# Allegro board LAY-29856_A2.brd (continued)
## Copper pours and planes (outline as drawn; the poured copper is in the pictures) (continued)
GND on TOP (solid shape): 50.31,35.8 51.45,35.8 51.72,35.53 51.75,35.42 51.66,35.36 51.36,35.21 51.26,34.9 51.26,34.87 50.79,34.4 50.79,33.64 49.72,32.57 49.61,32.55 49.55,32.65 49.55,33.53 49.64,33.53 49.64,33.78 49.68,33.78 49.68,34.29 49.64,34.29 49.64,34.8 49.68,34.8 49.68,35.31 49.64,35.31 49.64,35.56 49.56,35.56 49.56,35.81 50.3,35.81
GND on TOP (solid shape): 72.67,49.89 72.67,49.28 73.42,49.28 73.42,49.15 72.8,49.15 72.8,48.96 71.57,48.96 71.48,49.01 71.49,49.11 71.52,49.18 71.6,49.22 71.63,49.3 71.63,49.5 71.6,49.59 71.52,49.63 71.39,49.81 71.21,49.93 71.15,50.01 71.18,50.1 71.36,50.28 72.29,50.28
GND on TOP (solid shape): 118.99,61.08 118.75,60.62 118.93,60.13 118.95,60.02 118.86,59.96 118.03,59.96 117.96,60.02 117.94,60.13 118.03,60.2 118.59,60.2 118.59,61.22 118.53,61.27 118.52,61.35 118.54,61.42 118.54,61.5 118.54,61.52 118.88,61.86 118.99,61.86
GND on TOP (solid shape): 14.86,32.27 14.92,32.36 15.03,32.34 17.23,30.15 17.22,30.12 17.41,29.48 18.05,29.29 18.08,29.29 18.39,28.99 18.67,28.99 18.67,28.86 20.7,28.86 20.7,28.99 21.1,28.99 21.2,28.92 21.17,28.81 20.95,28.59 20.95,28.32 20.7,28.32 20.7,27.3 20.95,27.3 20.95,26.29 19.22,26.29 14.86,30.65
GND on TOP (solid shape): 105.73,48.2 105.84,48.23 105.9,48.13 105.9,47.35 95.81,37.26 95.79,37.26 95.39,37.06 95.38,36.61 95.38,36.51 95.3,36.46 95.2,36.46 95.12,36.51 95.12,36.61 95.17,36.91 95.01,37.17 95.01,37.48
GND on TOP (solid shape): 38.41,27.21 38.83,26.99 39.28,27.16 39.54,27.16 39.63,27.11 39.63,27.01 39.58,26.71 39.74,26.46 39.74,25.72 43.93,21.53 43.93,18.52 43.87,18.43 43.76,18.45 43.56,18.65 43.56,21.44 37.97,27.04 37.95,27.15 38.04,27.21
GND on TOP (solid shape): 81.27,24.24 81.03,24.24 81.03,24.28 80.52,24.28 80.52,24.24 80.26,24.24 80.26,24.02 80.15,24.02 79.87,23.74 79.87,23.67 79.81,23.57 79.7,23.6 79.66,23.63 79.61,23.71 79.64,23.79 79.69,23.83 79.75,23.92 79.77,24.02 79.77,24.26 79.75,24.36 79.69,24.45 79.69,24.45 79.66,24.56 79.75,24.62 79.96,24.83 80.01,24.92 80.03,25.02 80.03,25.13 81.27,25.13
GND on TOP (solid shape): 84.41,32.06 84.43,31.95 84.34,31.89 83.95,31.89 83.87,31.93 83.86,32.02 83.63,32.52 83.1,32.4 82.94,32.4 82.86,32.44 82.84,32.53 82.84,32.76 82.71,32.96 82.69,32.98 82.69,33 81,34.69 81,35.29 81.18,35.29
GND on TOP (solid shape): 9.73,49.74 9.76,49.65 9.81,49.58 10.15,49.24 10.15,48.38 9.84,47.86 10.19,47.35 10.23,47.28 10.31,47.24 10.52,47.24 10.6,47.28 10.64,47.35 10.72,47.39 10.79,47.44 10.89,47.46 10.95,47.37 10.95,46.48 9.9,46.48 8.76,47.62 8.76,47.98 8,48.75 8,49.42 8.36,49.78 9.73,49.78
GND on TOP (solid shape): 121.14,62.93 121.21,62.82 121.31,62.74 121.33,62.71 121.33,62.67 121.31,62.63 120.98,62.2 121.14,61.69 121.14,60.62 120.49,59.96 119.9,59.96 119.81,60.02 119.83,60.13 120,60.74 119.56,61.19 119.52,61.2 119.52,61.86 119.61,61.86 119.61,62.89 120.49,62.89 120.49,62.93
GND on TOP (solid shape): 8.75,55.77 9.26,55.44 9.78,55.74 11.87,55.74 12.07,55.62 12.3,55.62 12.39,55.6 12.43,55.52 12.43,54.62 12.39,54.54 12.3,54.52 12.16,54.53 12.02,54.5 12.01,54.5 11.65,54.5 11.65,54.61 10.92,54.61 10.92,54.84 10.65,55.12 8.4,55.12 8.33,55.04 8.22,55.02 8.15,55.11 8.15,55.77
GND on TOP (solid shape): 14.44,49.24 14.52,49.27 14.6,49.21 14.81,49.01 15.1,48.99 15.19,48.97 15.23,48.89 15.23,46.97 14.88,46.62 14.69,46.62 14.32,46.79 13.98,46.57 13.9,46.53 13.82,46.55 13.73,46.64 13.78,46.69 13.79,46.69 14.15,47.11 13.82,47.54 13.78,47.55 13.78,48.58
GND on TOP (solid shape): 22.81,57.97 22.85,57.96 22.86,57.91 22.93,57.63 23.19,57.51 23.72,57.51 23.93,57.45 24.15,57.51 24.16,57.52 24.29,57.52 24.29,57.4 24.38,57.4 24.38,57.19 23.71,56.53 23.63,56.53 23.55,56.57 23.53,56.66 23.4,57.09 22.95,57.17 22.94,57.16 21.51,57.16 21.41,57.26 21.38,57.37 21.48,57.43 21.72,57.43 21.72,57.65 21.83,57.65 22.15,57.97 22.79,57.97
GND on TOP (solid shape): 76.9,43.62 83.51,43.62 83.77,43.37 83.79,43.26 83.7,43.19 83.36,43.19 83.16,42.99 82.9,43.24 82.81,43.3 82.71,43.32 82.46,43.32 82.36,43.3 82.27,43.24 82.14,43.11 82.11,43.08 82.04,43.04 81.96,43.07 81.91,43.11 81.83,43.17 81.72,43.19 76.69,43.19 75.04,44.84 74.45,44.84 74.45,45.32 74.16,45.61 73.69,45.61 73.48,45.4 73.46,45.38 73.44,45.35 73.37,45.3 73.28,45.33 73.21,45.4 73.13,45.46 73.03,45.48 72.63,45.48 72.32,45.79 72.3,45.9 72.39,45.96 74.57,45.96
GND on TOP (solid shape): 124.98,37.82 125.05,37.92 125.16,37.88 125.98,37.46 126.8,37.88 126.92,37.92 126.99,37.82 126.99,36.31 126.36,35.68 126.36,34.93 126.14,34.93 126.14,34.31 125.88,34.05 125.68,34.05 125.6,34.1 125.6,34.2 125.55,34.7 125.05,34.82 125.04,34.81 124.94,34.81 124.94,34.93 123.97,34.93 123.97,35.2 124.98,36.21
GND on TOP (solid shape): 138.57,57.55 138.68,57.57 138.75,57.48 138.75,53.67 137.61,52.54 137.52,52.51 137.45,52.58 137.43,52.63 137.43,52.8 137.6,53.23 137.41,53.64 137.37,53.72 137.41,53.8 137.58,54.38 137.13,54.79 137.1,54.81 137.08,54.85 137.06,55.01 136.97,55.16 136.95,55.24 137,55.32 137,56.09 137.11,56.09
GND on TOP (solid shape): 40.93,29.84 41.02,29.78 40.99,29.66 40.74,28.55 41.79,28.1 41.81,28.11 41.87,28.05 43.11,28.05 43.2,27.95 43.31,27.86 43.31,27.51 43.2,27.42 43.11,27.32 41.87,27.32 41.86,27.31 41.2,27.31 40.55,27.95 39.28,27.95 39.19,28.03 39.09,28.08 39.05,28.16 38.96,28.19 38.76,28.19 38.69,28.17 38.64,28.12 38.63,28.09 38.47,28.09 38.43,28.12 38.44,28.17 38.48,28.22 38.48,29.74 38.59,29.84
GND on TOP (solid shape): 64.52,22.84 65.02,22.84 65.02,22.88 65.53,22.88 65.53,22.84 66.04,22.84 66.04,22.88 66.29,22.88 66.29,22.51 66.3,22.51 66.38,22.47 66.4,22.37 66.8,21.79 67.21,22.37 67.22,22.47 67.3,22.51 67.44,22.51 67.53,22.47 67.54,22.37 67.52,22.29 67.51,22.2 67.52,22.17 66.95,21.6 64.65,21.6 64.57,21.64 64.55,21.73 64.52,22.04 64.3,22.24 64.29,22.25 64.26,22.27 64.26,22.88 64.52,22.88
GND on TOP (solid shape): 26.63,59.29 26.8,59.26 26.97,59.29 26.98,59.3 27.05,59.3 27.05,57.8 26.77,57.8 26.76,57.84 26.71,57.89 26.64,57.91 26.44,57.91 26.36,57.88 26.32,57.8 25.98,57.39 26.13,56.88 26.15,56.86 26.15,56.66 25.78,56.66 25.78,54.76 27.31,54.76 27.31,55.07 27.37,55.16 27.48,55.14 27.99,54.64 28.01,54.53 27.91,54.46 26.73,54.46 26.73,52.72 24.24,52.72 21.39,55.57 21.37,55.68 21.46,55.74 24.04,55.74 25.17,56.87 25.17,57.4 25.25,57.4 25.25,57.66 25.29,57.66 25.29,58.17 25.25,58.17 25.25,58.67 25.29,58.67 25.29,59.18 25.25,59.18 25.25,59.3 26.62,59.3
GND on TOP (solid shape): 59.83,34.29 59.89,34.38 60,34.36 60.72,33.64 61.61,33.64 65.35,29.9 69.53,29.9 69.6,29.86 69.63,29.78 69.85,29.39 70.28,29.53 70.54,29.53 73.76,26.31 73.76,13.98 78.41,9.33 83.9,9.33 84.38,9.81 84.4,9.81 84.79,10.04 84.65,10.46 84.65,10.57 84.84,10.57 84.84,11.19 84.96,11.19 84.96,10.44 85.08,10.44 85.08,8.89 73.29,8.89 73.29,25.98 73.3,25.99 73.33,26.16 73.3,26.33 73.29,26.34 73.29,26.45 71.41,28.33 70.01,28.33 68.87,29.48 65.57,29.48 62.27,32.78 62.07,32.78 62.07,32.89 60.36,32.89 60.36,32.46 60.24,32.35 60.13,32.33 60.07,32.42 60.07,33.24 59.83,33.24
GND on TOP (solid shape): 51.72,30.33 51.82,30.3 52.31,29.81 52.31,29.39 52.31,29.38 52.38,28.93 52.82,28.79 52.91,28.78 52.95,28.69 52.95,28.21 53.41,27.74 53.18,27.51 52.61,27.51 52.2,27.92 52.04,27.92 52.04,28.7 50.32,28.7 50.32,28.54 49.66,28.54 49.66,28.56 49.4,28.56 49.4,28.59 48.89,28.59 48.89,28.56 48.64,28.56 48.64,28.07 47.34,28.07 47.25,28.14 47.28,28.25 47.62,29.01 47.19,29.72 47.15,29.83 47.24,29.91 51.13,29.91 51.23,30 51.25,30 51.5,30.05 51.65,30.26
GND on TOP (solid shape): 64.93,29.01 64.95,28.89 64.85,28.83 62.01,28.83 61.2,28.02 61.1,28 61.03,28.09 60.98,28.25 60.88,28.38 60.85,28.47 60.91,28.55 61.1,28.67 61.23,28.86 61.31,28.9 61.34,28.98 61.34,29.18 61.31,29.27 61.23,29.31 61.18,29.4 61.11,29.48 61.1,29.5 61.1,29.56 61.11,29.57 61.18,29.65 61.23,29.74 61.31,29.79 61.34,29.87 61.34,30.07 61.31,30.16 61.23,30.2 61.15,30.33 61.04,30.44 61,30.5 61.02,30.58 61.04,30.61 61.47,30.61 61.47,31.62 61.04,31.62 61.01,31.67 60.97,31.71 60.96,31.82 61.05,31.88 62.05,31.88
GND on TOP (solid shape): 111.69,14.62 111.95,14.36 111.95,13.86 110.99,13.86 110.46,14.16 109.97,13.82 109.89,13.77 109.85,13.69 109.85,13.49 109.89,13.4 109.97,13.36 110.03,13.25 110.11,13.16 110.15,13.08 110.11,13 110.03,12.91 109.97,12.8 109.89,12.76 109.85,12.67 109.85,12.47 109.89,12.39 109.97,12.35 110.47,12 111,12.31 111.95,12.31 111.95,11.81 111.69,11.55 111.69,11.43 108.18,11.43 106.27,13.34 105.13,13.34 104.92,13.55 104.9,13.67 104.99,13.73 106.38,13.73 106.38,14.04 106.51,14.04 106.94,14.47 106.94,14.65 107.02,14.74 111.69,14.74
GND on TOP (solid shape): 87.58,20.05 87.62,20.03 87.62,19.99 87.62,19.93 87.62,19.8 87.62,19.8 87.62,16.52 88.9,16.52 89.14,16.27 89.14,15.6 88.63,15.1 88.63,12.56 88.43,12.36 88.41,12.37 88.13,12.37 87.89,12.24 87.82,12.22 87.38,12.38 86.93,12.22 86.86,12.24 86.81,12.28 86.75,12.32 86.75,12.46 87.87,13.58 87.87,15.13 87.96,15.26 88,15.42 88,16 87.86,16.3 87.55,16.39 87.5,16.39 87.5,16.4 84.21,16.4 84.21,16.39 84.13,16.4 84.1,16.41 84.09,16.44 84.08,16.52 84.09,16.52 84.09,17.8 83.96,17.8 83.96,18.02 84.09,18.02 84.09,19.8 84.08,19.8 84.09,19.88 84.1,19.91 84.13,19.93 84.21,19.93 84.21,19.92 87.5,19.92 87.5,20.06
GND on TOP (solid shape): 59.5,22.13 59.57,22.08 59.69,21.93 59.84,21.83 59.89,21.75 59.97,21.72 60.17,21.72 60.26,21.75 60.3,21.83 60.4,21.88 60.49,21.96 60.7,21.96 60.78,21.92 60.8,21.83 60.83,21.52 61.05,21.32 61.06,21.31 64.25,18.12 64.25,16.82 64.23,16.77 64.16,16.7 64.06,16.73 62.94,17.84 60.56,17.84 60.48,17.89 60.47,17.99 60.51,18.16 60.48,18.34 60.47,18.35 60.47,18.41 60.56,18.41 60.56,18.67 60.6,18.67 60.6,19.18 60.56,19.18 60.56,19.43 59.04,19.43 59.04,19.68 59.07,19.68 59.07,20.19 59.04,20.19 59.04,20.39 59.08,20.4 59.62,20.96 59.31,21.67 59.31,22.02 59.36,22.06 59.41,22.1
GND on TOP (solid shape): 86.09,11.4 86.17,11.33 86.26,11.29 86.3,11.21 86.39,11.18 86.59,11.18 86.67,11.21 86.71,11.29 86.79,11.33 86.86,11.38 86.93,11.41 87,11.38 87.07,11.33 87.15,11.29 87.19,11.21 87.27,11.18 87.48,11.18 87.56,11.21 87.6,11.29 87.68,11.33 87.75,11.38 87.82,11.41 87.89,11.38 87.96,11.33 88.04,11.29 88.08,11.21 88.16,11.18 88.37,11.18 88.45,11.21 88.49,11.29 88.57,11.33 88.64,11.38 88.71,11.41 88.78,11.38 88.85,11.33 88.93,11.29 88.97,11.21 89.05,11.18 89.26,11.18 89.34,11.21 89.38,11.29 89.44,11.32 89.5,11.35 89.61,11.36 89.66,11.27 89.66,11.19 89.92,11.19 89.92,11.16 90.42,11.16 90.42,11.19 90.68,11.19 90.68,10.44 91.44,10.44 91.44,9 91.33,8.89 85.87,8.89 85.87,10.44 85.98,10.44 85.98,11.41 86.08,11.41
GND on TOP (solid shape): 70.46,22.38 70.54,22.35 70.56,22.27 70.8,21.84 71.29,21.91 71.3,21.92 71.37,21.92 71.37,21.87 72.12,21.87 72.12,14.97 69.99,12.84 68.21,12.84 68.13,12.88 68.11,12.97 68.12,13.11 68.09,13.25 68.09,13.26 68.09,16.42 66.82,17.69 66.82,19.59 65.43,20.98 65.42,21.01 65.42,21.07 67.17,21.07 67.89,21.8 67.92,21.79 68.05,21.81 68.17,21.86 68.27,21.86 68.33,21.77 68.33,20.86 68.57,20.86 68.57,19.01 68.53,18.94 68.45,18.91 67.86,17.56 69.04,18.45 69.03,18.48 69.1,18.55 69.1,20.86 69.58,20.86 69.58,18.92 69.47,18.92 69.47,17.4 70.99,17.4 70.99,18.92 70.12,18.92 70.12,20.86 70.36,20.86 70.36,22.38
GND on TOP (solid shape): 18.9,54.52 18.96,54.61 19.07,54.59 19.83,53.83 20.72,53.83 23.26,51.29 26.03,51.29 26.11,51.25 26.13,51.16 26.11,51.02 26.14,50.87 26.15,50.86 26.15,49.84 26.11,49.8 25.43,49.8 25.35,49.87 25.25,49.93 25.2,50.01 25.12,50.04 24.92,50.04 24.83,50.01 24.79,49.93 24.73,49.9 24.67,49.86 24.03,49.86 24.03,50.1 22.51,50.1 22.51,48.83 24.03,48.83 24.03,49.07 24.55,49.07 24.58,49.04 24.62,48.99 24.62,48.9 24.54,48.9 24.54,47.88 24.62,47.88 24.62,46.48 23.54,46.48 23.54,46.93 24.03,46.93 24.03,48.2 22.51,48.2 22.51,46.93 23,46.93 23,46.48 22.88,46.48 22.88,46.23 22.84,46.23 22.84,45.72 22.88,45.72 22.88,45.57 22.02,45.57 22.02,45.62 21.82,45.96 21.42,45.99 21.41,45.99 18.91,45.99 18.81,46.05 18.83,46.16 18.92,46.25 18.92,46.74 21.44,46.74 21.97,47.27 21.97,51.54 21.7,51.82 20.45,51.82 20.45,52.07 19.43,52.07 19.43,51.82 19.03,51.82 18.95,51.9 18.92,51.98 18.98,52.06 19.23,52.48 18.93,52.86 18.9,52.87
GND on TOP (solid shape): 94.1,20.79 94.2,20.76 97.57,17.4 103.67,17.4 103.88,17.18 103.88,16.75 102.16,16.75 102.16,16.44 102.04,16.44 101.23,15.63 96.88,15.63 96.24,16.26 94.15,16.26 94.07,16.29 94.04,16.37 93.95,16.69 93.7,16.91 93.66,16.99 93.57,17.02 93.37,17.02 93.29,16.99 93.24,16.91 93.12,16.84 93.03,16.74 92.93,16.7 92.85,16.77 92.74,16.95 92.58,17.1 92.58,17.45 92.9,17.96 92.69,18.53 92.66,18.61 92.69,18.68 92.9,19.25 92.58,19.76 92.58,20.12 92.74,20.26 92.85,20.44 92.93,20.51 93.03,20.47 93.12,20.37 93.24,20.3 93.29,20.22 93.37,20.19 93.57,20.19 93.66,20.22 93.7,20.3 93.92,20.47 94.03,20.71
GND on TOP (solid shape): outline of 168 points within 128.79,53.61 138.29,60.81
GND on TOP (solid shape): 46.33,64.74 46.34,64.73 46.7,64.47 47.11,64.68 47.18,64.73 47.27,64.7 48.1,63.87 48.99,63.87 49.02,63.83 49.02,62.36 49,62.36 49,61.85 49.02,61.85 49.02,61.11 49.77,60.36 49.77,58.38 51.04,58.38 51.14,58.31 51.12,58.2 51.05,58.11 51.01,58 51.01,57.99 49.94,56.92 49.94,54.73 49.94,54.23 50.4,54.07 50.49,54.05 50.53,53.97 50.53,50.12 50.38,49.66 50.75,49.35 50.8,49.35 50.8,40.53 51.08,40.26 52.3,40.26 52.58,40.53 52.58,54.84 52.61,54.91 52.68,54.94 52.76,54.94 52.95,54.75 52.95,40.5 51.75,39.3 51.65,39.28 51.58,39.35 51.21,39.67 50.78,39.45 50.71,39.39 50.62,39.42 50.1,39.94 50.1,53.65 49.7,54.06 49.7,57.74 49.32,58.12 49.3,58.22 49.38,58.29 49.46,58.38 49.56,58.38 49.56,58.47 49.58,58.49 49.58,60.26 49.56,60.28 49.56,60.31 49.53,60.31 48.39,61.45 48.39,61.95 45.34,65 45.34,65.26 45.18,65.42 45.18,65.52 45.56,65.52
GND on TOP (solid shape): outline of 200 points within 25.41,46.06 36.45,51.29
GND on TOP (solid shape): outline of 113 points within 85.69,42.74 96.38,48.13
GND on TOP (solid shape): outline of 113 points within 72.6,61.35 81.5,64.38
GND on TOP (solid shape): outline of 116 points within 31.28,33.54 45.16,42.53
GND on TOP (solid shape): outline of 185 points within 72.48,45.73 91.83,48.61
GND on TOP (solid shape): outline of 109 points within 53.09,22.96 60.31,30.72
GND on TOP: 4.45,51.94 5.59,51.94 5.71,51.82 5.71,48.01 5.46,47.75 4.45,47.75 4.32,47.88 4.32,51.82
GND on TOP: 8.51,49.91 9.65,49.91 9.78,49.78 9.78,48.26 9.65,48.13 8.64,48.13 8,48.77 8,49.4
GND on BOTTOM: 139.49,0.51 0.51,0.51 0.51,89.49 139.49,89.49 ; 3 cut-outs
P3V3_SDA on BOTTOM: 119.51,82.55 119.63,82.68 120.52,82.68 121.28,81.92 129.03,81.92 130.18,80.77 130.18,78.61 130.43,78.36 132.59,78.36 132.84,78.11 132.84,77.47 131.89,76.52 130.11,76.52 128.33,74.74 128.33,72.07 126.24,69.98 125.86,69.98 125.6,70.23 125.6,70.74 127.13,72.26 127.13,75.82 128.4,77.09 128.4,79.12 127.51,80.01 125.98,80.01 125.35,80.64 122.43,80.64 121.79,80.01 121.79,79.38 121.67,79.25 121.16,79.25 121.03,79.38 121.03,79.76 119.51,81.28
P5V_SDA on TOP: 132.46,74.68 133.22,73.91 133.65,73.91 133.71,73.86 134.32,73.86 134.37,73.81 134.37,73.67 134.31,73.62 134.08,73.62 133.96,73.5 133.96,73.28 133.89,73.21 133.53,73.21 132.84,72.52 131.06,72.52 130.81,72.77 130.81,74.3 131.19,74.68
VDD_SOC_IN on TOP: 55.24,54.74 62.74,54.74 63.5,53.98 63.5,41.02 62.48,40.01 56.26,40.01 56.13,40.13 56.13,41.4 56.26,41.53 60.96,41.53 61.98,42.55 61.98,52.45 61.59,52.83 55.24,52.83 55.12,52.96 55.12,54.61
VDD_SOC_IN on TOP: 43.69,58.93 45.34,57.28 45.34,56.52 45.21,56.39 43.94,56.39 43.31,57.02 39.24,57.02 38.99,57.28 35.94,57.28 35.69,57.53 35.69,59.56 35.94,59.82 40.13,59.82 40.26,59.69 40.26,59.18 40.51,58.93
VDD_SOC_IN on BOTTOM: 42.93,58.8 48.13,58.8 48.64,58.29 48.64,57.02 50.8,54.86 57.28,54.86 57.4,54.74 57.4,53.34 57.28,53.21 49.15,53.21 45.85,56.52 42.93,56.52 42.67,56.77 42.67,58.55
(no net) on TOP: 0.64,0.64 0.64,89.41 42.8,89.41 43.05,89.66 65.91,89.66 66.17,89.41 139.49,89.41 139.49,0.64 ; 27 cut-outs
DC_5V_IN on TOP: 17.65,10.92 17.91,10.67 17.91,8.89 18.16,8.64 18.67,8.64 18.8,8.51 18.8,3.3 18.54,3.05 13.59,3.05 12.83,3.81 11.05,3.81 10.67,4.19 10.67,10.79 10.79,10.92
DCDC_3V3 on TOP: 96.9,25.02 96.9,21.97 96.77,21.84 95.38,21.84 94.87,22.35 94.87,23.88 94.36,24.38 91.31,24.38 91.19,24.51 91.19,26.29 91.31,26.42 95.5,26.42
DCDC_3V3 on TOP: 124.97,63.12 124.97,51.56 124.84,51.44 123.57,51.44 123.44,51.56 123.44,63.12 123.57,63.25 124.84,63.25
DCDC_3V3 on TOP: 92.84,2.67 91.57,3.94 67.56,3.94 60.07,11.43 60.07,12.19 59.05,13.21 40.51,13.21 37.21,16.51 37.21,21.08 30.99,27.3 30.99,37.21 30.35,37.85 26.16,37.85 25.91,38.1 25.91,40.51 26.16,40.77 33.66,40.77 36.45,37.97 36.45,32.26 36.96,31.75 42.8,31.75 43.56,32.51 45.97,32.51 46.1,32.38 46.1,31.5 45.97,31.37 45.34,31.37 44.07,30.1 38.48,30.1 38.23,29.84 38.23,28.32 38.1,28.19 37.34,28.19 37.21,28.07 37.21,27.43 43.31,21.34 43.31,18.54 44.58,17.27 54.1,17.27 54.48,16.89 62.48,16.89 70.74,8.64 91.44,8.64 91.69,8.89 91.69,12.19 91.57,12.32 90.04,12.32 89.92,12.45 89.92,15.88 90.04,16 90.42,16 91.19,15.24 91.19,14.35 91.44,14.1 92.96,14.1 93.22,13.84 93.22,8.51 96.14,5.59 107.95,5.59 108.46,6.1 117.86,6.1 120.02,8.26 120.02,25.27 120.27,25.53 123.57,25.53 123.89,25.21 123.89,6.41 120.14,2.67
DCDC_3V3 on BOTTOM: 28.57,38.61 26.29,38.61 21.21,43.69 21.21,55.5 22.48,56.77 22.48,59.94 22.61,60.07 24.89,60.07 25.02,59.94 25.02,56.26 24.51,55.75 24.51,45.34 28.96,40.89 28.96,38.99
DCDC_3V3 on BOTTOM: 91.76,15.68 91.76,15.18 91.31,14.73 90.17,14.73 90.04,14.86 90.04,19.43 93.73,23.11 96.39,23.11 96.52,22.99 96.52,20.45
DCDC_3V3 on BOTTOM: 90.55,26.8 94.23,26.8 94.36,26.67 94.36,25.91 94.23,25.78 92.2,25.78 90.81,24.38 88.52,24.38 88.01,24.89 88.01,25.65 88.52,26.16 89.92,26.16
DCDC_3V3 on BOTTOM: 117.47,29.34 118.36,30.23 123.19,30.23 129.79,36.83 129.79,42.29 121.16,50.93 109.09,50.93 107.44,52.58 107.44,72.39 105.41,74.42 105.41,77.85 105.79,78.23 113.28,78.23 113.54,77.98 113.54,74.68 109.86,70.99 109.86,54.74 111.51,53.09 124.08,53.09 135.13,42.04 135.13,35.69 123.19,23.75 118.36,23.75 117.47,24.64
DCDC_OUT on TOP: 42.16,65.28 42.29,65.15 42.29,61.34 42.04,61.09 41.53,61.09 41.27,60.83 41.27,60.45 41.15,60.33 38.99,60.33 38.86,60.2 36.2,60.2 35.69,60.71 35.69,65.15 35.81,65.28
MCU_DCDC_IN on TOP: 50.42,61.72 50.42,60.58 50.29,60.45 50.04,60.45 49.28,61.21 49.28,63.75 49.4,63.88 50.93,63.88 51.05,63.75 51.05,62.36
NVCC_GPIO_3V3 on TOP: 47.75,34.29 47.88,34.42 47.88,35.18 48.01,35.31 48.51,35.31 48.64,35.18 48.64,32.89 48.51,32.77 45.47,32.77 45.34,32.89 45.34,34.04 45.59,34.29
NVCC_GPIO_3V3 on TOP: 62.99,55.75 52.58,55.75 52.32,55.5 52.32,40.64 52.2,40.51 51.18,40.51 51.05,40.64 51.05,56.2 52.2,57.34 54.99,57.34 55.28,57.05 65.79,57.05 66.67,56.17 66.67,54.86 66.17,54.36 66.17,40.77 66.04,40.64 64.9,40.64 64.77,40.77 64.77,53.98
NVCC_GPIO_3V3 on BOTTOM: 52.45,37.97 49.91,35.43 49.91,33.02 49.4,32.51 45.97,32.51 45.85,32.64 45.85,34.04 45.97,34.16 47.62,34.16 47.88,34.42 47.88,36.83 50.8,39.75 50.8,41.53 51.05,41.78 52.32,41.78 52.45,41.66
NVCC_SD on TOP: 21.59,66.8 25.15,66.8 25.27,66.67 25.27,64.77 25.15,64.64 21.59,64.64 21.46,64.77 21.46,66.67
SDA_USBSHIELD on TOP: 116.71,89.41 128.14,89.41 128.27,89.28 128.27,87.5 128.14,87.38 120.65,87.38 119.63,86.36 116.71,86.36 116.46,86.61 116.46,89.15
SDRAM_3V3 on BOTTOM: 90.55,58.93 106.68,58.93 107.19,58.42 107.19,52.45 106.43,51.69 102.11,51.69 101.47,51.05 98.81,51.05 98.55,51.31 98.55,56.52 98.68,56.64 100.33,56.64 100.58,56.39 100.58,53.85 100.84,53.59 103.63,53.59 104.9,54.86 104.9,56.64 104.65,56.9 90.55,56.9 90.3,57.15 90.3,58.67
N99781671 on TOP: 45.09,65.15 45.09,64.9 48.13,61.85 48.13,61.34 49.32,60.15 49.32,58.59 49.28,58.55 49.02,58.55 48.01,59.56 48.01,59.82 47.5,60.33 46.23,60.33 45.85,60.71 45.85,60.96 45.72,61.09 43.18,61.09 43.05,61.21 43.05,65.15 43.18,65.28 44.96,65.28
N99781747 on TOP: 24.13,36.2 26.16,36.2 26.42,36.45 26.42,37.08 26.67,37.34 30.35,37.34 30.61,37.08 30.61,31.62 30.48,31.5 26.16,31.5 25.91,31.75 23.62,31.75 23.5,31.88 23.5,34.29 23.75,34.54 23.75,35.81
N99781762 on TOP: 22.23,31.11 22.62,31.11 22.65,31.08 22.65,29.21 23.29,28.57 23.88,28.57 24.13,28.32 24.13,26.42 24,26.29 21.34,26.29 21.21,26.42 21.21,28.49 22.18,29.46 22.18,31.07
N99781791 on TOP: 25.91,30.86 30.48,30.86 30.61,30.73 30.61,28.96 30.35,28.7 24.26,28.7 24.13,28.83 24.13,29.21 24.64,29.72 25.4,29.72 25.78,30.1 25.78,30.73
N99816488 on TOP: 130.56,25.27 137.67,25.27 138.18,24.77 138.18,0.89 137.92,0.64 130.81,0.64 130.18,1.27 130.18,24.89
N99833003 on TOP: 0.64,38.35 0.51,38.48 0.51,50.67 0.76,50.93 3.68,50.93 3.94,50.67 3.94,48.77 2.92,47.75 2.92,38.61 2.67,38.35
N100054172 on TOP: 26.04,9.27 28.32,9.27 28.57,9.53 31.24,9.53 31.75,10.03 31.75,12.32 32,12.57 36.2,12.57 36.45,12.32 36.45,4.32 36.2,4.06 33.15,4.06 30.86,1.78 26.67,1.78 26.29,2.16 26.29,5.21 25.91,5.59 25.91,9.14
N100054299 on TOP: 19.43,9.78 19.18,9.78 19.05,9.65 19.05,4.06 19.18,3.94 19.56,3.94 21.72,1.78 25.53,1.78 25.78,2.03 25.78,7.11 25.65,7.24 24,7.24 23.75,7.49 23.75,9.78 23.62,9.91 19.56,9.91
N100054652 on TOP: 28.57,18.29 29.46,17.4 31.24,17.4 31.5,17.14 31.5,10.16 31.11,9.78 28.96,9.78 28.7,10.03 28.7,11.81 25.15,15.37 25.15,21.46 25.27,21.59 28.45,21.59 28.57,21.46
N101139052 on TOP: 8.51,54.86 10.54,54.86 10.67,54.74 10.67,51.44 10.29,51.05 9.91,51.05 9.78,50.93 9.78,50.16 9.65,50.04 9.53,50.04 9.46,50.1 9.46,50.34 9.37,50.43 9.13,50.43 9.05,50.51 9.05,51.02 8.38,51.69 8.38,54.74

Small or netless copper shapes (teardrops, artwork), in the pictures only: 26 on TOP

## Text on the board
BOTTOM: 170-29856_REV A2 | 5 | ARTWORK BOTTOM
Ref Des/Silkscreen Bottom: 7 | SILKSCREEN BOTTOM
User.Comments: 3 | 6 | SOLDMASK BOTTOM | SOLDMASK TOP | 1/1 | 1
TOP: 4 | ARTWORK TOP
Ref Des/Silkscreen Top: 2 | SILKSCREEN TOP | MIMXRT1020-EVK
DIMENSION: 56 MILS | If the angle of PCB board outline is circular,please use this kind of break out area | If not use it,please delete it before you gerber out | If the angle of PCB board outline is right angle,please use this kind of break out area | AS usual,please use the 0.8MM stamp Via | SCALE: NONE | .062" THK +/- 10% | LAYER 1  TOP LAYER          1 oz. | LAYER 2  BOTTOM LAYER       1 oz. | FINISHED Cu WEIGHT | 0 | DETAIL A | LAYER STACKUP
FABRICATION_NOTES: 16. | 8. | 1. THIS DRAWING SPECIFIES THE REQUIREMENTS FOR A | 2. THE PWB MUST BE LEAD FREE ASSEMBLY PROCESS COMPATIBLE AND MUST BE ABLE TO HANDLE | 3. BASE MATERIAL - LAMINATE AND PREPREG SHALL MEET IPC-4101B-26, 83 or 98 | Tg - MUST BE GREATER THAN OR EQUAL TO 150 DEGREES CELSIUS. | Td - MUST BE GREATER THAN OR EQUAL TO 330 DEGREES CELSIUS. | 4. COPPER FOIL WEIGHT - SEE STACKUP DETAIL 'A' | 5. CHARACTERISTIC IMPEDANCE - SEE DETAIL 'B' | 6. MINIMUM CONDUCTIVE WIDTH/SPACING TO BE .00X"/.00X" | 7. PLATING FINISH - BOTH SIDES ENIG (ELECTROLESS NICKEL IMMERSION GOLD): | 8. ALL THROUGH HOLE VIAS MAY BE PLATED SHUT. | - MUST BE UL RECOGNIZED AND MUST HAVE AN ID THAT CONFORMS TO UL94V-0 | 9. SOLDERMASK - GREEN COLOR (TAIYO OR EQUIVALENT), BOTH SIDES. | 10. SILKSCREEN - WHITE EPOXY INK, BOTH SIDES.  NO SILK ON PADS. | 11. ELECTRICAL TEST - 100% IPCD356. | 12. PRINTED WIRING BOARD IS TO BE INDIVIDUALLY BAGGED. | 13. DRC'S MUST BE RUN ON THE GERBER BEFORE BUILDING BOARDS, | UNLESS PRIOR APPROVAL IS GIVEN IN WRITING BY NXP | 14. ADD TEARDROPS TO ALL SIGNAL LAYERS. | 15. SOLDER SAMPLES TO BE PROVIDED. | 16. BASIC GRID INCREMENT AT 1:1 IS .0001. | 17. SUPPLIER MARKINGS - ON SOLDER SIDE ONLY, WHERE SHOWN. | MODIFICATION OF SOLDERMASK IS NOT ALLOWED WITHOUT WRITTEN PERMISSION FROM NXP | WITH SPECIFICATION IPC-A-600 CLASS 2 (LATEST REVISION). | A MINIMUM OF 5 CYCLES AT 260 DEGREES CELSIUS FOR 10 SECONDS. | 18. THE PWB WILL BE MARKED AS LEAD FREE BY USE OF AN INK STAMP Pb | 19. THE PWB WILL BE MARKED AS LEAD FREE PROCESS COMPATIBLE BY USE OF AN INK STAMP 260 C | 21. FINISHED PCB MUST BE PANELIZED FOR ASSEMBLY ACCORDING TO CONTRACT MANUFACTURING REQUIREMENT. | ADDITION OF .25" RAILS AND .125" NON-PLATED TOOLING HOLES ARE AT THE DISCRETION | OF CONTRACT MANUFACTURER AND FAB HOUSE. | PANELIZATION MUST BE APPROVED BY NXP | 2.540-6.350 MICRON (100-250 MICROINCH) OF NICKEL. | .05080-.232 MICRON (2-8 MICROINCH) OF GOLD OVER | PRINTED WIRING BOARD IN ACCORDANCE | 20. ALL PLATED AND NON-PLATED THROUGH HOLES ARE TO BE DRILLED AT PRIMARY DRILL STEP. | ALL HOLE LOCATION TOLERANCES ARE TO BE +/-.002 IN REFERENCE TO THE PRIMARY DATUM. | DETAIL B | IMPEDANCE REQUIREMENTS | IMPEDANCE TOLERANCE IS 10%
User.5: 8 | PASTEMASK_BOTTOM
User.6: 1 | PASTEMASK_TOP
User.12: 6501 WILLIAM CANNON DRIVE WEST | AUSTIN. TEXAS 78735 USA | SHEET | THIS DOCUMENT CONTAINS INFORMATION | PROPRIETARY TO FREESCALE AND SHALL | NOT BE USED FOR ENGINEERING DESIGN | PROCUREMENT OR MANUFACTURE IN WHOLE | OR IN PART WITHOUT THE CONSENT OF | NXP. | OF 8 | FILM | NAME | DATE | 03-01-18 | ___ PUBI (PUBLIC INFORMATION) | ___ NIUO (NXP INTERNAL USE ONLY) | ___ NCP (NXP CONFIDENTIAL PROPRIETARY) | NUMBER | X | MIMXRT1020-EVK | 170-29856      REV A2 | NXP SEMICONDUCTOR
User.17: FIGURE | SIZE | 8.0 | 26.0 | 28.0 | 30.0 | 36.0 | 40.0 | 41.0 | 45.0 | 63.0 | 139.0 | 22.0 | 59.0 | 118.0 | 59.0x20.0 | 118.0x31.0 | 137.8x31.5 | DRILL CHART: TOP to BOTTOM | ALL UNITS ARE IN MILS | TOLERANCE | +3.0/-3.0 | +2.0/-2.0 | PLATED | NON-PLATED | QTY | 1647 | 10 | 6 | 2 | 26 | 46 | 20 | 4 | 1
User.19: Trace Width | (Mils) | Impedance | (Ohms) | Trace Spacing | "Airgap" | L1 | L2 | 5.00 | 50 | 4.2 | 6.00 | 100 | 4.70 | 90 | Layers | Single Ended | Differential
User.20: ___ PUBI (PUBLIC INFORMATION) | ___ NIUO (NXP INTERNAL USE ONLY) | ___ NCP (NXP CONFIDENTIAL PROPRIETARY) | THIS DOCUMENT CONTAINS INFORMATION | PROPRIETARY TO FREESCALE AND SHALL | NOT BE USED FOR ENGINEERING DESIGN | PROCUREMENT OR MANUFACTURE IN WHOLE | OR IN PART WITHOUT THE CONSENT OF | NXP. | 6501 WILLIAM CANNON DRIVE WEST  AUSTIN, TEXAS 78735 USA | X | Shawn Shi | Albert Li | 03-01-18 | 10-30-17 | SHAWN | A | A2 | UPDATE SD AND MCU POWER | LAY-29856 | FAB-29856 | 170-29856 | PRINTED WIRING BOARD | MIMXRT1020-EVK | NXP SEMICONDUCTOR
